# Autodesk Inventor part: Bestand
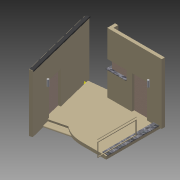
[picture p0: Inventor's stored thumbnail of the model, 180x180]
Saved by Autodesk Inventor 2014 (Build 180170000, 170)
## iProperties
Created: 2013-09
Part Number: Bestand
Material: Generisch
Document SubType Name: Modeling
Designer: Stefan Tammegger
Density: 1 g/cm^3
Appearance: Vorgabe
Author: Stefan Tammegger
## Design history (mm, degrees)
sketch "Skizze1"
  geometry: L1 (0, 0)-(0, 500); L2 (0, 0)-(3500, 0); L3 (3500, 200)-(200, 200); L4 (200, 200)-(200, 500); L5 (0, 500)-(200, 500); L6 (3500, 0)-(3500, 200)
  constraints: 12 end point, 4 perpendicular, 1 vertical, 1 other
  dimensions: "d0" = 500 distance of L1.start L1.end; "d1" = 3500 distance of L1.start L2.end; "d2" = 200 distance between parallel lines of L3 L2
extrude "Extrusion1" new body sketch "Skizze1" distance "d3" = 3800; taper "d4" = 0 deg
sketch "Skizze2"
  geometry: L1 (3500, 0)-(0, 0) reference; L2 (0, 0)-(0, 3800) reference; L3 (2970, 30)-(3340, 30); L4 (3340, 30)-(3340, 0); L5 (3340, 0)-(2970, 0); L6 (2970, 0)-(2970, 30)
  constraints: 8 end point, 2 parallel, 1 collinear, 1 horizontal, 1 perpendicular
  dimensions: "d5" = 370 distance of L4.end L5.end; "d6" = 30 distance of L3.end L4.end; "d7" = 2970 distance between parallel lines of L2 L6
extrude "Extrusion2" new body sketch "Skizze2" distance "d8" = 3300; taper "d9" = 0 deg
sketch "Skizze3"
  geometry: L1 (3500, 0)-(0, 0) reference; L2 (0, 0)-(0, 3800) reference; L3 (1580, 2065)-(2550, 2065); L4 (2550, 2065)-(2550, 0); L5 (2550, 0)-(1580, 0); L6 (1580, 0)-(1580, 2065)
  constraints: 8 end point, 2 parallel, 1 collinear, 1 horizontal, 1 perpendicular
  dimensions: "d10" = 970 distance of L4.end L5.end; "d11" = 2065 distance of L3.end L4.end; "d12" = 1580 distance between parallel lines of L6 L2
extrude "Extrusion3" cut sketch "Skizze3" distance "d13" = 150; taper "d14" = 0 deg
sketch "Skizze4"
  geometry: L1 (0, -3800)-(0, 0) reference; L2 (1580, -1735)-(2550, -1735) reference; L3 (0, -1735)-(1240, -1735); L4 (1240, -1735)-(1240, -2305); L5 (1240, -2305)-(0, -2305); L6 (0, -2305)-(0, -1735)
  constraints: 8 end point, 2 collinear, 2 parallel, 1 horizontal, 1 perpendicular
  dimensions: "d15" = 1240 distance of L4.end L5.end; "d16" = 570 distance of L3.end L4.end
extrude "Extrusion4" cut sketch "Skizze4" distance "d17" = 150; taper "d18" = 0 deg
sketch "Skizze5"
  geometry: L1 (0, 500)-(3800, 500) reference; L2 (2065, 150)-(1495, 150); L3 (1495, 150)-(1495, 500); L4 (1495, 500)-(2065, 500); L5 (2065, 500)-(2065, 150)
  constraints: 8 end point, 2 parallel, 1 horizontal, 1 perpendicular, 1 point on line
extrude "Extrusion5" cut sketch "Skizze5" distance "d19" = 150; taper "d20" = 0 deg
sketch "Skizze6"
  geometry: L1 (1240, 0)-(0, 0) reference; L2 (1240, 0)-(1240, 150) reference; L3 (150, 150)-(150, 500) reference; L4 (0, 0)-(0, 500) reference; L5 (150, 500)-(-50, 500); L6 (-50, 500)-(-50, -50); L7 (-50, -50)-(1240, -50); L8 (1240, -50)-(1240, 150); L9 (1240, 150)-(150, 150); L10 (150, 150)-(150, 500)
  constraints: 12 end point, 3 perpendicular, 2 collinear, 1 parallel
  dimensions: "d21" = 50 distance between parallel lines of L6 L4; "d22" = 50 distance between parallel lines of L7 L1
extrude "Extrusion6" new body sketch "Skizze6" distance "d23" = 25; taper "d24" = 0 deg
workplane "Arbeitsebene1"
sketch "Skizze7"
  geometry: L1 (0, 0)-(0, 150) reference; L2 (-950, 0)-(0, 0) reference; C1 r 60 at (-150, -70); 1 further point
  constraints: 1 centre point
  dimensions: "d26" = 120 diameter of C1; "d27" = 150 distance from line of C1.centre L1; "d28" = 70 distance from line of L2 C1.centre
extrude "Extrusion7" new body sketch "Skizze7" distance "d29" = 400; taper "d30" = 0 deg
sketch "Skizze8"
  geometry: L1 (0, 0)-(370, 0) reference; L2 (0, 0)-(0, -3300) reference; L3 (160, -1280)-(200, -1280); L4 (200, -1280)-(200, -3780); L5 (200, -3780)-(160, -3780); L6 (160, -3780)-(160, -1280); 1 further point
  constraints: 8 end point, 2 parallel, 1 horizontal, 1 perpendicular
  dimensions: "d31" = 40 distance of L4.end L5.end; "d32" = 2500 distance of L3.end L4.end; "d33" = 160 distance between parallel lines of L2 L6; "d34" = 1280 distance between parallel lines of L1 L3
extrude "Extrusion8" new body sketch "Skizze8" distance "d35" = 890; taper "d36" = 0 deg
sketch "Skizze9"
  geometry: L1 (40, 0)-(40, 890) reference; L2 (0, 890)-(40, 890) reference; C1 r 21 at (20, 1022); 1 further point
  constraints: 1 centre point
  dimensions: "d37" = 42 diameter of C1; "d38" = 132 distance from line of C1.centre L2; "d39" = 20 distance from line of L1 C1.centre
extrude "Extrusion9" join sketch "Skizze9" stored distance "d40" = 890; taper "d41" = 0 deg
sketch "Skizze10"
  geometry: L1 (1485, 0)-(5985, 0); L2 (1594.72, 440.064)-(385.111, -4411.414); L3 (1594.72, 440.064)-(6594.72, 440.064); L4 (0, 0)-(1485, 0); L5 (579.17, -4459.799)-(1764.885, 295.844); L6 (1764.885, 295.844)-(1594.72, 440.064); L7 (579.17, -4459.799)-(385.111, -4411.414)
  constraints: 14 end point, 2 horizontal, 2 parallel, 1 equal length, 1 perpendicular
  dimensions: "d48" = 5000 distance of L2.start L2.end; "d49" = 104 deg angle of L2 L3; "d50" = 1485 distance of L4.start L1.start; "d51" = 0 distance from line of L2 L1.start; "d52" = 200 distance between parallel lines of L5 L2
extrude "Extrusion10" new body sketch "Skizze10" stored distance "d53" = 890; taper "d54" = 0 deg
sketch "Skizze11"
  geometry: L1 (1594.72, 440.064)-(385.111, -4411.414) reference; L2 (385.111, -4411.414)-(579.17, -4459.799) reference; L3 (579.17, -4459.799)-(1764.885, 295.844) reference; L4 (1764.885, 295.844)-(1594.72, 440.064) reference; L5 (-1580, 0)-(0, 0) reference; L6 (0, 0)-(1594.72, 0); 1 further point
  constraints: 2 end point, 2 point on line, 1 collinear
workpoint "Arbeitspunkt1"
sketch "Skizze12"
  geometry: L1 (1735, 3804.973)-(1735, 3950.517) reference; L2 (1785, 1446.464)-(3880, 1446.464); L3 (3880, 1446.464)-(3880, 2496.464); L4 (3880, 2496.464)-(1785, 2496.464); L5 (1785, 2496.464)-(1785, 1446.464); 2 further points
  constraints: 8 end point, 2 parallel, 1 horizontal, 1 perpendicular
  dimensions: "d55" = 2095 distance of L4.end L3.end; "d56" = 1050 distance of L3.end L2.end; "d57" = 50 distance from line of L5 L1.start; "d58" = 2050 distance from line of point (3800, 4546.464) L4
extrude "Extrusion11" cut sketch "Skizze12" distance "d59" = 150; taper "d60" = 0 deg
workplane "Arbeitsebene2"
sketch "Skizze13"
  geometry: L1 (0, 0)-(150, 0) reference; L2 (0, 0)-(0, -1446.464) reference; C1 r 60 at (-70, -210); 1 further point
  constraints: 1 centre point
  dimensions: "d62" = 120 diameter of C1; "d63" = 70 distance from line of L2 C1.centre; "d64" = 210 distance from line of L1 C1.centre
extrude "Extrusion12" new body sketch "Skizze13" distance "d65" = 400; taper "d66" = 0 deg
workplane "Arbeitsebene3"
sketch "Skizze14"
  geometry: L1 (0, 2500)-(0, 0) reference; L2 (0, 2500)-(-890, 2500) reference; L3 (-890, 0)-(-890, 2500) reference; L4 (0, 0)-(-890, 0) reference; L5 (-850, 2460)-(-40, 2460); L6 (-40, 2460)-(-40, 40); L7 (-40, 40)-(-850, 40); L8 (-850, 40)-(-850, 2460); 1 further point
  constraints: 8 end point, 3 other
  dimensions: "d68" = 40 distance between parallel lines of L3 L8
extrude "Extrusion13" cut sketch "Skizze14" distance "d69" = 400; taper "d70" = 0 deg
sketch "Skizze15"
  geometry: L1 (880.586, -3044.205)-(735.042, -3007.917) reference; L2 (735.042, -3007.917)-(385.111, -4411.414) reference; L3 (385.111, -4411.414)-(579.17, -4459.799) reference; L4 (579.17, -4459.799)-(1764.885, 295.844) reference; L5 (1764.885, 295.844)-(1594.72, 440.064) reference; L6 (1594.72, 440.064)-(989.06, -1989.106) reference; L7 (989.06, -1989.106)-(1134.604, -2025.395) reference; L8 (1134.604, -2025.395)-(880.586, -3044.205) reference; 1 further point
extrude "Extrusion14" join sketch "Skizze15" stored distance "d71" = 400; taper "d72" = 0 deg
sketch "Skizze16"
  geometry: L1 (-50, 1446.464)-(-200, 1446.464) reference; L2 (-200, 1446.464)-(-200, 0) reference; L3 (0, 0)-(0, 4901.23) reference; L4 (-200, 1326.464)-(-1300, 1326.464); L5 (-4522.667, 3468.702)-(-3724.325, 266.726) reference; L6 (-3724.325, 266.726)-(-2559.97, 557.032); L7 (-2559.97, 557.032)-(-2069.754, 679.257); L8 (-2069.754, 679.257)-(-1640.889, 868.231); L9 (-1640.889, 868.231)-(-1300, 1326.464); L10 (-3724.325, 266.726)-(-3974.486, 204.354); L11 (-1883.333, 4332.884)-(-5085.309, 3534.542) reference; L12 (-3974.486, 204.354)-(-4821.213, 3600.389); L13 (-4821.213, 3600.389)-(-1706.297, 4671.839); L14 (-1706.297, 4671.839)-(0, 4901.23); L15 (0, 4901.23)-(0, 1302.194); L16 (0, 1302.194)-(-200, 1326.464); 1 further point
  constraints: 16 end point, 3 perpendicular, 3 point on line, 1 collinear, 3 other
  dimensions: "d73" = 1100 distance of L4.start L4.end; "d74" = 120 distance between parallel lines of L1 L4; "d75" = 1200 distance of L5.end L6.end
extrude "Extrusion15" new body sketch "Skizze16" distance "d76" = 200; taper "d77" = 0 deg
sketch "Skizze17"
  geometry: L1 (-200, 1446.464)-(-200, 0) reference; L2 (-200, 0)-(0, 0) reference; L3 (0, 0)-(0, 4901.23) reference; L4 (-200, 1326.464)-(0, 1302.194) reference; L5 (0, 1302.194)-(-200, 1326.464); 1 further point
  constraints: 2 end point, 1 collinear
extrude "Extrusion16" join sketch "Skizze17" stored distance "d78" = 200; taper "d79" = 0 deg
sketch "Skizze18"
  geometry: L1 (4080, -3673.536)-(4080, -5000) reference; L2 (3880, -3673.536)-(4080, -3673.536) reference; L3 (3880, -3553.536)-(3880, -3673.536) reference; L4 (3990, -3673.536)-(4004.574, -3746.699); L5 (4004.574, -3746.699)-(3990.319, -3806.438); L6 (3990.319, -3806.438)-(4009.38, -3859.696); L7 (4009.38, -3859.696)-(3983.505, -3887.476); L8 (3983.505, -3887.476)-(4007.276, -3937.696); L9 (4007.276, -3937.696)-(3990, -3973.101); L10 (3990, -3973.101)-(4013.02, -4026.457); L11 (4013.02, -4026.457)-(3990, -4071.271); L12 (3990, -4071.271)-(4080, -4079.319); L13 (4080, -4079.319)-(4080, -3673.536); L14 (4080, -3673.536)-(3990, -3673.536); 1 further point
  constraints: 4 end point, 2 point on line, 1 parallel, 1 perpendicular, 3 other
  dimensions: "d80" = 110 distance of L2.start L4.start
extrude "Extrusion17" new body sketch "Skizze18" stored distance "d81" = 200; taper "d82" = 0 deg
workplane "Arbeitsebene4"
feature "Trennen1"
sketch "Skizze19"
  geometry: L1 (200, 3705)-(0, 3705) reference; L2 (200, 3705)-(200, 0) reference; L3 (24.702, 3725)-(240, 3725); L4 (240, 3725)-(240, 3645); L5 (240, 3645)-(223.128, 3661.872); L6 (24.702, 3723)-(238, 3723); L7 (238, 3723)-(238, 3649.828); L8 (238, 3649.828)-(224.542, 3663.287); L9 (223.128, 3661.872)-(224.542, 3663.287); L10 (24.702, 3725)-(24.702, 3723); 1 further point
  constraints: 16 end point, 4 perpendicular, 1 parallel, 2 other
  dimensions: "d84" = 80 distance of L3.end L4.end; "d85" = 20 distance between parallel lines of L3 L1; "d86" = 2 distance between parallel lines of L3 L6; "d89" = 40 distance between parallel lines of L4 L2; "d90" = 45 deg angle of L7 L8; "d91" = 23.86112 distance of L4.end L5.end
extrude "Extrusion18" new body sketch "Skizze19" stored distance "d87" = 200; taper "d88" = 0 deg
sketch "Skizze20"
  geometry: L1 (-2550, 0)-(-2550, 150) reference; L2 (-2550, 150)-(-1580, 150) reference; L3 (-1580, 150)-(-1580, 0) reference; L4 (-1580, 0)-(0, 0) reference; L5 (0, 0)-(0, 500) reference; L6 (0, 500)-(-200, 500) reference; L7 (-200, 500)-(-200, 200) reference; L8 (-200, 200)-(-3500, 200) reference; L9 (-3500, 200)-(-3500, 0) reference; L10 (-3500, 0)-(-2550, 0) reference
extrude "Extrusion19" join sketch "Skizze20" stored distance "d92" = 200; taper "d93" = 0 deg
node "Volumenkörper1"
node "Volumenkörper2"
node "Volumenkörper3"
node "Volumenkörper4"
node "Volumenkörper5"
node "Volumenkörper6"
node "Volumenkörper7"
node "Volumenkörper8"
node "Volumenkörper9"
node "Volumenkörper10"
